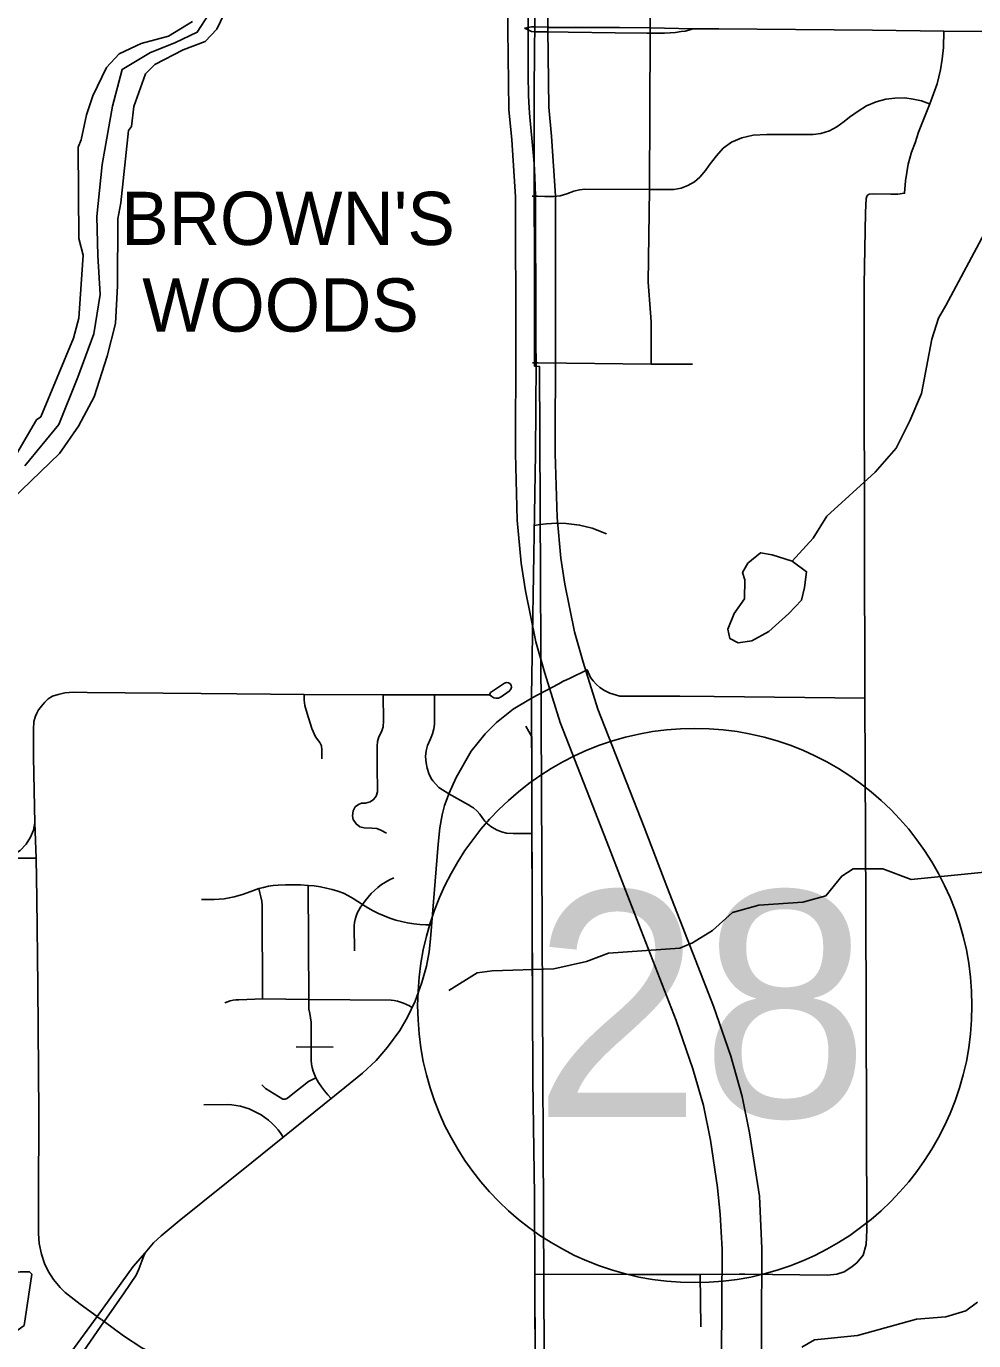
# Model space of a CAD drawing. Extents: x -1403959 to 81668, y -1400582 to 11018.
# Drawn here: x 6697.8 to 6835.6, y 7840.8 to 8032.1 of the extents above; entities that cross this region are included whole.
import ezdxf

# ---------------------------------------------------------------- set-up
doc = ezdxf.new("R2010")
doc.units = 0
for name, color, linetype in [('tdCiRRCL', 7, 'Continuous'), ('tdCiSectNmbr', 7, 'Continuous'), ('tdCiSectTwpRng', 7, 'Continuous'), ('tdCoClipBndry', 7, 'Continuous'), ('tdCoDivCarto', 7, 'Continuous'), ('tdCoPlotFrame', 7, 'Continuous'), ('tdCoSurfAsphalt', 7, 'Continuous'), ('tdCoSurfBitum', 7, 'Continuous'), ('tdCoTwpNameTxt', 7, 'Continuous')]:
    doc.layers.add(name, color=color, linetype=linetype)

msp = doc.modelspace()

# ---------------------------------------------------------------- linework, layer by layer
at = {"layer": 'tdCiRRCL'}
for points in [[(6770.82, 8033.28), (6770.81, 8031.66), (6770.82, 8030.43), (6770.82, 8029.68), (6770.82, 8028.55), (6770.83, 8025.03), (6770.88, 8022.04), (6770.96, 8020.17), (6771.05, 8018.87), (6771.36, 8015.83), (6771.67, 8012.14), (6771.79, 8010.21), (6771.91, 8007.37), (6771.92, 7987.87), (6771.95, 7985.96), (6771.97, 7983.14), (6771.89, 7969.94), (6771.31, 7934.62), (6771.39, 7904.39), (6771.41, 7897.57), (6771.44, 7890.2), (6771.51, 7878.7), (6771.75, 7861.97), (6771.78, 7850.5), (6771.85, 7837.99)], [(6771.85, 7837.99), (6771.78, 7850.5), (6771.75, 7861.97), (6771.51, 7878.7), (6771.44, 7890.2), (6771.41, 7897.57), (6771.39, 7904.39), (6771.31, 7934.62), (6771.89, 7969.94), (6771.97, 7983.14), (6771.95, 7985.96), (6771.92, 7987.87), (6771.91, 8007.37), (6771.79, 8010.21), (6771.67, 8012.14), (6771.36, 8015.83), (6771.05, 8018.87), (6770.96, 8020.17), (6770.88, 8022.04), (6770.83, 8025.03), (6770.82, 8028.55), (6770.82, 8029.68), (6770.82, 8030.43), (6770.81, 8031.66), (6770.82, 8033.28)]]:
    msp.add_lwpolyline(points, dxfattribs=at)
at = {"layer": 'tdCiSectNmbr'}
for points in [[(6773.77, 8031.96), (6771.74, 8032.01), (6771.32, 8032.03), (6770.81, 8031.93)], [(6770.81, 8031.93), (6770.29, 8031.83)], [(6770.29, 8031.83), (6770.81, 8031.58)], [(6770.81, 8031.58), (6771.32, 8031.33), (6771.84, 8031.32), (6773.76, 8031.28)], [(6773.76, 8031.28), (6776.62, 8031.23), (6783.47, 8031.17)], [(6783.48, 8031.95), (6773.87, 8031.95), (6773.77, 8031.96)], [(6783.47, 8031.17), (6788.09, 8031.12), (6788.57, 8031.12)], [(6788.58, 8031.86), (6788.58, 8031.86), (6784.1, 8031.95), (6783.48, 8031.95)], [(6788.57, 8031.12), (6788.57, 8031.12), (6790.65, 8031.11), (6791.47, 8031.15), (6792.28, 8031.22), (6793.09, 8031.33), (6793.66, 8031.42), (6794.22, 8031.55), (6794.78, 8031.72)], [(6794.78, 8031.72), (6790.64, 8031.82), (6788.58, 8031.86)], [(6794.78, 8031.72), (6795.52, 8031.74), (6798.55, 8031.74)], [(6798.55, 8031.74), (6820.94, 8031.55), (6831.29, 8031.38), (6842.34, 8031.32)], [(6829.25, 8020.81), (6830.35, 8023.74), (6830.82, 8025.78), (6831.06, 8027.3), (6831.23, 8029.03), (6831.29, 8031.38)], [(6823.59, 8007.66), (6824.62, 8007.68), (6825.6, 8007.8), (6825.73, 8009.64), (6826.13, 8012.04), (6826.62, 8013.8), (6827.13, 8015.17), (6827.63, 8016.69), (6829.25, 8020.81)], [(6819.72, 7982.34), (6819.72, 7994.49), (6819.89, 8005.03), (6820, 8007.04), (6820.15, 8007.47), (6820.42, 8007.67), (6821.09, 8007.74), (6823.59, 8007.66)], [(6819.8, 7934.34), (6819.72, 7982.34)], [(6776.08, 7936.86), (6776.82, 7937.19), (6779.4, 7938.46), (6779.89, 7937.32), (6780.28, 7936.83), (6780.73, 7936.36), (6781.24, 7935.87), (6781.91, 7935.44), (6782.72, 7935.07), (6784.18, 7934.62), (6792.87, 7934.6), (6797.87, 7934.59), (6811.09, 7934.45), (6819.8, 7934.34)], [(6771.32, 7934.31), (6775.3, 7936.4), (6776.03, 7936.83)], [(6776.03, 7936.83), (6776.08, 7936.86)], [(6715.09, 7853.61), (6716.32, 7855.06), (6717.4, 7856.07), (6720.06, 7858.26), (6730.62, 7866.76), (6744.12, 7877.67), (6746.72, 7879.75), (6748.71, 7881.59), (6750.35, 7883.56), (6752.15, 7885.96), (6753.25, 7887.93), (6754.36, 7890.24), (6755.37, 7892.97), (6756.02, 7895.33), (6756.41, 7897.43), (6756.61, 7899.29), (6757.71, 7913.07), (6757.97, 7915.47), (6758.3, 7917.36), (6758.64, 7918.7), (6759.03, 7919.72), (6759.27, 7920.43), (6760.34, 7922.79), (6762.52, 7926.62), (6764.54, 7929.13), (6766.23, 7930.81), (6768.66, 7932.71), (6771.14, 7934.22), (6771.29, 7934.29)], [(6771.29, 7934.29), (6771.32, 7934.31)], [(6817.98, 7851.64), (6818.64, 7852.18), (6819.57, 7853.25), (6819.98, 7854.8), (6820.08, 7856.93), (6819.93, 7904.01), (6819.8, 7934.34)], [(6715.09, 7853.61), (6713.35, 7851.62), (6708.11, 7844.34)], [(6709.13, 7843.63), (6712.03, 7847.81), (6713.76, 7850.38), (6714.15, 7851.23), (6714.92, 7853.19)], [(6714.92, 7853.19), (6715.09, 7853.61)], [(6771.78, 7850.5), (6785.69, 7850.45), (6795.87, 7850.46), (6801.52, 7850.51), (6801.96, 7850.51)], [(6801.96, 7850.51), (6802.34, 7850.51), (6814.38, 7850.38), (6815.72, 7850.51), (6816.79, 7850.86), (6817.79, 7851.48)], [(6817.79, 7851.48), (6817.98, 7851.64)], [(6708.11, 7844.34), (6704.28, 7839.09), (6698.85, 7830.41), (6697.97, 7829.14)], [(6698.84, 7828.58), (6701.73, 7832.94), (6709.07, 7843.55)], [(6708.72, 7843.9), (6709.11, 7843.61), (6711.92, 7841.54), (6714.6, 7839.79), (6715.67, 7839.26), (6717.02, 7838.72), (6718.7, 7838.36), (6719.91, 7838.25), (6722.47, 7838.19), (6726.78, 7838.11), (6734.64, 7838.13), (6749.45, 7838.05), (6761.01, 7838.02)], [(6709.07, 7843.55), (6709.11, 7843.61)], [(6709.11, 7843.61), (6709.13, 7843.63)]]:
    msp.add_lwpolyline(points, dxfattribs=at)
at = {"layer": 'tdCiSectTwpRng'}
for points in [[(6788.73, 7982.96), (6788.73, 7989.12), (6788.62, 7990.42), (6788.3, 7994.85), (6788.46, 8008.35), (6788.57, 8031.12), (6788.58, 8031.49), (6788.58, 8031.86), (6788.58, 8038.26), (6788.65, 8044.45), (6788.39, 8044.75), (6788.19, 8044.8)], [(6771.91, 8007.37), (6772.19, 8007.37), (6773.26, 8007.35), (6774.57, 8007.34), (6775.5, 8007.45), (6776.43, 8007.73), (6777.46, 8008.09), (6778.3, 8008.33), (6779.08, 8008.38), (6788.46, 8008.35), (6792.01, 8008.35), (6793.09, 8008.57), (6794.06, 8008.96), (6795.03, 8009.48), (6795.82, 8010.16), (6796.62, 8011.13), (6797.15, 8011.89), (6798.2, 8013.27), (6799.21, 8014.35), (6800.42, 8015.23), (6801.93, 8015.86), (6803.57, 8016.26), (6805.57, 8016.37), (6810.58, 8016.36), (6812.3, 8016.34), (6813.4, 8016.49), (6814.65, 8016.88), (6815.75, 8017.48), (6816.79, 8018.26), (6817.6, 8018.88), (6818.85, 8019.77), (6820.03, 8020.52), (6821.46, 8021.1), (6822.88, 8021.52), (6824.16, 8021.64), (6825.61, 8021.69), (6826.83, 8021.51), (6828.06, 8021.26), (6829.24, 8020.82)], [(6829.24, 8020.82), (6829.25, 8020.81)], [(6771.41, 8007.38), (6771.85, 8007.37)], [(6771.85, 8007.37), (6771.91, 8007.37)], [(6771.44, 7983.14), (6771.92, 7983.14)], [(6771.92, 7983.14), (6771.97, 7983.14)], [(6771.97, 7983.14), (6772.27, 7983.14), (6788.73, 7982.96), (6794.73, 7982.96)], [(6771.75, 7959.48), (6772.26, 7959.55)], [(6772.26, 7959.55), (6772.55, 7959.59), (6773.47, 7959.72), (6774.95, 7959.82), (6776.37, 7959.75), (6778.31, 7959.52), (6780.14, 7959.05), (6782.22, 7958.23)], [(6764.92, 7934.81), (6765.18, 7934.81), (6765.51, 7934.55), (6765.83, 7934.38), (6766.14, 7934.31), (6766.49, 7934.35), (6766.88, 7934.52), (6768.07, 7935.34), (6768.3, 7935.63), (6768.38, 7935.93), (6768.33, 7936.2), (6768.17, 7936.46), (6767.96, 7936.58), (6767.67, 7936.6), (6767.4, 7936.53), (6765.64, 7935.36), (6765.35, 7935.14), (6765.18, 7934.81)], [(6699.56, 7932.61), (6699.61, 7932.7), (6700.01, 7933.18), (6700.47, 7933.75), (6700.99, 7934.21), (6701.63, 7934.61), (6702.42, 7934.88), (6703.39, 7935.1), (6704.68, 7935.18), (6706.65, 7935.15), (6723.25, 7935)], [(6723.25, 7935), (6728.44, 7934.95)], [(6728.44, 7934.95), (6738.21, 7934.88)], [(6740.82, 7925.51), (6740.8, 7926.83), (6740.73, 7927.39), (6740.49, 7927.88), (6739.9, 7928.71), (6739.34, 7929.94), (6738.66, 7932.09), (6738.33, 7933.25), (6738.21, 7934.03), (6738.21, 7934.88)], [(6738.21, 7934.88), (6749.72, 7934.81), (6757.19, 7934.83)], [(6750.21, 7914.67), (6749.4, 7915.12), (6748.82, 7915.36), (6748.09, 7915.42), (6746.97, 7915.44), (6746.33, 7915.63), (6745.78, 7916.03), (6745.38, 7916.65), (6745.25, 7917.19), (6745.36, 7917.93), (6745.66, 7918.51), (6746.13, 7918.86), (6746.59, 7919.06), (6747.15, 7919.06), (6747.83, 7919.23), (6748.32, 7919.57), (6748.7, 7920.05), (6748.89, 7920.72), (6748.86, 7924.5), (6748.85, 7927.33), (6748.89, 7928.02), (6749.09, 7928.69), (6749.47, 7929.45), (6749.7, 7930.14), (6749.78, 7931.03), (6749.72, 7934.81)], [(6756.96, 7922.31), (6756.69, 7922.66), (6756.37, 7923.37), (6756.13, 7924.15), (6755.98, 7924.91), (6755.89, 7925.84), (6755.98, 7926.66), (6756.18, 7927.42), (6756.59, 7928.39), (6756.91, 7929.15), (6757.11, 7929.86), (6757.21, 7930.54), (6757.19, 7934.77)], [(6757.19, 7934.77), (6757.19, 7934.83)], [(6757.19, 7934.83), (6759.53, 7934.83), (6764.43, 7934.81)], [(6764.43, 7934.81), (6764.92, 7934.81)], [(6699.03, 7916.2), (6698.99, 7918.48), (6698.85, 7925.79), (6698.83, 7929.76), (6698.91, 7930.92), (6699.12, 7931.7), (6699.31, 7932.13), (6699.56, 7932.61)], [(6770.47, 7930.25), (6770.46, 7930.27)], [(6771.33, 7928.7), (6770.47, 7930.25)], [(6771.85, 7837.99), (6771.8, 7847.06), (6771.78, 7850.5), (6771.75, 7861.97), (6771.51, 7878.7), (6771.44, 7890.2), (6771.39, 7904.39), (6771.37, 7914.65), (6771.33, 7927.48), (6771.37, 7928.63), (6771.33, 7928.7)], [(6762.33, 7918.69), (6762.13, 7918.81), (6759.27, 7920.43), (6757.82, 7921.32), (6757.32, 7921.84), (6756.96, 7922.31)], [(6762.35, 7918.67), (6762.33, 7918.69)], [(6771.37, 7914.65), (6768.62, 7914.65), (6767.69, 7914.7), (6766.93, 7914.87), (6766.22, 7915.17), (6765.39, 7915.65), (6764.92, 7916.06), (6764.53, 7916.45), (6764.23, 7916.84), (6763.79, 7917.47), (6763.4, 7917.88), (6762.86, 7918.37), (6762.35, 7918.67)], [(6699.03, 7916.2), (6698.83, 7915.11), (6698.4, 7914.08), (6697.8, 7913.06), (6696.91, 7912.17), (6695.67, 7911.38), (6694.31, 7911.04)], [(6708.1, 7844.35), (6705.65, 7846.13), (6703.43, 7847.83), (6702.7, 7848.59), (6701.75, 7849.75), (6700.99, 7850.93), (6700.45, 7852.06), (6699.99, 7853.44), (6699.67, 7854.96), (6699.56, 7856.41), (6699.56, 7861.5), (6699.61, 7873.87), (6699.49, 7892.49), (6699.33, 7905.2), (6699.23, 7911.03), (6699.03, 7916.2), (6699.03, 7916.2)], [(6646.88, 7911.37), (6663.6, 7911.26), (6678.23, 7911.1), (6680.11, 7911.1), (6684.68, 7911.05), (6691.1, 7911), (6694.31, 7911.04), (6699.23, 7911.03)], [(6745.56, 7897.57), (6745.51, 7901.18), (6745.56, 7901.66), (6745.65, 7902.14), (6745.78, 7902.61), (6745.96, 7903.06), (6746.18, 7903.5), (6746.43, 7903.91), (6746.72, 7904.3), (6747.1, 7904.86), (6747.52, 7905.39), (6747.97, 7905.89), (6748.45, 7906.36), (6748.96, 7906.8), (6749.5, 7907.2), (6750.06, 7907.57), (6750.65, 7907.9), (6751.26, 7908.18)], [(6723.28, 7905.02), (6725.12, 7905.02), (6725.85, 7905.07), (6726.59, 7905.15), (6727.32, 7905.26), (6728.05, 7905.4), (6729.25, 7905.78), (6730.45, 7906.19), (6731.63, 7906.63), (6732.32, 7906.8), (6733.03, 7906.95), (6733.73, 7907.06), (6734.45, 7907.14), (6735.53, 7907.18), (6736.62, 7907.18), (6737.71, 7907.15), (6738.8, 7907.09), (6739.67, 7907.02), (6740.58, 7906.86), (6741.44, 7906.69), (6742.29, 7906.48), (6743.13, 7906.23), (6743.95, 7905.93), (6744.67, 7905.56), (6745.37, 7905.17), (6746.05, 7904.75), (6746.72, 7904.3), (6747.48, 7903.82), (6748.25, 7903.38), (6749.05, 7902.99), (6749.87, 7902.63), (6750.7, 7902.31), (6751.55, 7902.04), (6752.41, 7901.81), (6753.28, 7901.62)], [(6732.16, 7890.61), (6732.12, 7904.16), (6732.05, 7904.79), (6731.94, 7905.41), (6731.8, 7906.02), (6731.63, 7906.63)], [(6742.14, 7876.07), (6741.68, 7876.59), (6741.2, 7877.18), (6740.75, 7877.79), (6740.33, 7878.42), (6739.93, 7879.06), (6739.71, 7879.54), (6739.53, 7880.04), (6739.39, 7880.56), (6739.3, 7881.08), (6739.26, 7881.61), (6739.26, 7883.58), (6739.26, 7886.51), (6739.24, 7887.16), (6739.17, 7887.81), (6739.05, 7888.45), (6738.89, 7889.09), (6738.89, 7890.49), (6738.8, 7907.09)], [(6753.28, 7901.62), (6754.16, 7901.48), (6755.05, 7901.39), (6755.94, 7901.34), (6756.77, 7901.33)], [(6726.68, 7889.99), (6727.07, 7890.15), (6727.47, 7890.27), (6727.88, 7890.36), (6728.3, 7890.41), (6728.72, 7890.43), (6732.2, 7890.56), (6738.89, 7890.49), (6750.87, 7890.36), (6751.34, 7890.32), (6751.8, 7890.23), (6752.25, 7890.11), (6752.69, 7889.96), (6753.12, 7889.77), (6753.53, 7889.54), (6753.9, 7889.29)], [(6737.07, 7883.6), (6742.46, 7883.54)], [(6732.06, 7878.05), (6732.58, 7877.54), (6735.14, 7875.99), (6735.25, 7875.97), (6735.37, 7875.96), (6735.48, 7875.97), (6735.6, 7876), (6735.7, 7876.05), (6735.79, 7876.12), (6736.35, 7876.58), (6738.86, 7878.54), (6739.93, 7879.06)], [(6723.61, 7875.17), (6727.03, 7875.21), (6727.69, 7875.16), (6728.33, 7875.07), (6728.97, 7874.94), (6729.6, 7874.76), (6730.22, 7874.55), (6730.83, 7874.29), (6731.41, 7874), (6731.97, 7873.67), (6732.52, 7873.3)], [(6732.52, 7873.3), (6733.03, 7872.9), (6733.52, 7872.47), (6733.99, 7872), (6734.42, 7871.51), (6734.81, 7870.99), (6735.18, 7870.44)], [(6795.95, 7842.84), (6795.87, 7850.46)], [(6708.11, 7844.34), (6708.1, 7844.35)], [(6708.11, 7844.34), (6708.22, 7844.26), (6708.69, 7843.92)]]:
    msp.add_lwpolyline(points, dxfattribs=at)
at = {"layer": 'tdCoClipBndry'}
msp.add_lwpolyline([(6772.58, 8111.64), (6771.71, 8023.1), (6771.76, 7982.65), (6772.45, 7982.6), (6773.16, 7838.81)], dxfattribs=at)
at = {"layer": 'tdCoDivCarto'}
for points in [[(6768.06, 8061.81), (6767.88, 8031.66), (6768.03, 8020), (6768.44, 8015.57), (6768.97, 8007.31), (6769.02, 7985.93), (6768.96, 7969.92), (6769.23, 7960.23), (6769.82, 7954), (6770.45, 7949.96), (6771.95, 7942.54), (6773.26, 7937.95), (6775.48, 7930.8), (6782.29, 7913.43), (6785.55, 7904.87), (6792.35, 7887.44), (6794.8, 7880.41), (6796.31, 7875.03), (6797.33, 7870.01), (6798.39, 7863.11), (6798.78, 7859.18), (6799.04, 7854.13), (6798.9, 7830.6)], [(6773.86, 8061.84), (6773.68, 8031.66), (6773.83, 8020.34), (6774.22, 8016.1), (6774.78, 8007.43), (6774.82, 7985.99), (6774.76, 7969.95), (6775.03, 7960.64), (6775.58, 7954.71), (6776.17, 7950.94), (6777.57, 7943.99), (6778.83, 7939.56), (6780.95, 7932.75), (6787.68, 7915.57), (6790.98, 7906.91), (6797.78, 7889.5), (6800.32, 7882.21), (6801.96, 7876.35), (6803.04, 7871.07), (6804.46, 7861.84), (6804.84, 7854.24), (6804.7, 7830.76)]]:
    msp.add_lwpolyline(points, dxfattribs=at)
at = {"layer": 'tdCoSurfAsphalt'}
msp.add_circle((6795.07, 7889.6), 40.33, dxfattribs=at)
at = {"layer": 'tdCoSurfBitum'}
for points in [[(6690.09, 7957.89), (6702.63, 7969.93), (6705.39, 7973.89), (6707.69, 7978.16), (6709.54, 7984.11), (6710.77, 7988.84), (6711.08, 7994.34), (6711.1, 8004.11), (6711.57, 8006.4), (6712.66, 8016.93), (6713.12, 8017.54), (6713.43, 8020.44), (6715.12, 8025.17), (6716.49, 8026.54), (6720.62, 8028.67), (6723.83, 8029.88), (6725.52, 8031.71), (6728.12, 8037.2)], [(6696.07, 7969.33), (6699.28, 7974.82), (6699.9, 7975.28), (6704.65, 7986.72), (6705.42, 7989.62), (6706.05, 7998.78), (6705.45, 8001.22), (6705.32, 8014.5), (6705.78, 8015.57), (6706.55, 8019.24), (6707.47, 8021.98), (6709.47, 8026.1), (6711.3, 8028.08), (6714.51, 8029.6), (6718.49, 8030.66), (6722, 8032.79)], [(6809.21, 7954.27), (6812.27, 7957.62), (6814.26, 7960.82), (6821.3, 7967.22), (6824.36, 7970.72), (6826.35, 7974.69), (6828.04, 7978.65), (6829.58, 7986.59), (6830.51, 7989.64), (6831.58, 7991.47), (6837.56, 8002.61), (6840.92, 8004.89), (6845.51, 8006.71), (6851.62, 8007.77), (6856.96, 8007.45), (6864.14, 8006.82), (6867.35, 8005.75), (6869.79, 8003.76), (6874.82, 8000.84), (6876.04, 8001.15), (6878.18, 8002.97), (6879.56, 8005.11), (6880.94, 8006.63), (6882.01, 8006.63)], [(6809.21, 7954.27), (6811.34, 7952.73), (6811.03, 7950.44), (6810.57, 7948.61), (6808.73, 7946.63), (6805.83, 7944.04), (6803.38, 7942.67), (6801.39, 7942.37), (6800.17, 7942.99), (6799.87, 7944.36), (6800.79, 7946.65), (6802.32, 7948.78), (6802.33, 7951.53), (6802.03, 7952.6), (6802.79, 7953.97), (6804.63, 7955.5), (6806.31, 7955.19), (6809.21, 7954.27)], [(6837.22, 7909.01), (6826.53, 7907.96), (6822.41, 7909.5), (6818.13, 7909.51), (6816.45, 7908.44), (6814.15, 7905.55), (6810.79, 7904.64), (6804.37, 7904.19), (6800.55, 7903.13), (6797.64, 7900.54), (6794.74, 7898.72), (6792.91, 7897.96), (6782.52, 7897.22), (6779.31, 7896), (6774.57, 7894.95), (6765.56, 7894.66), (6763.42, 7894.36), (6759.29, 7891.77)], [(6695.22, 7850.54), (6696.9, 7850.84), (6698.27, 7850.84), (6698.58, 7850.53), (6697.49, 7843.05), (6695.2, 7841.38), (6694.28, 7842.29), (6694.13, 7843.36), (6692, 7846.57), (6691.85, 7848.1), (6695.22, 7850.54)], [(6836.18, 7846.41), (6834.49, 7845.19), (6831.59, 7844.28), (6827.31, 7843.98), (6818.76, 7841.56), (6812.49, 7840.96), (6810.66, 7839.9)]]:
    msp.add_lwpolyline(points, dxfattribs=at)
at = {"layer": 'tdCoTwpNameTxt'}
msp.add_lwpolyline([(6697.6, 7968.14), (6702.52, 7974.14), (6705.29, 7981.06), (6707.6, 7987.37), (6708.53, 7993.07), (6708.22, 7998.75), (6708.06, 8004.45), (6708.83, 8011.98), (6710.36, 8020.46), (6711.74, 8025.84), (6715.89, 8028.31), (6719.43, 8029.69), (6722.66, 8031.23), (6724.35, 8033.85)], dxfattribs=at)

# ---------------------------------------------------------------- texts
at = {"layer": 'tdCoPlotFrame'}
for s, p in [("BROWN'S", (6711.61, 8000.29)), ('WOODS', (6714.67, 7987.68))]:
    msp.add_text(s, height=7.738, rotation=359.9908, dxfattribs=at).set_placement(p)
at = {"layer": 'tdCoSurfAsphalt'}
msp.add_text('28', height=32.887, dxfattribs=at).set_placement((6771.52, 7873.37))

doc.saveas('drawing.dxf')
